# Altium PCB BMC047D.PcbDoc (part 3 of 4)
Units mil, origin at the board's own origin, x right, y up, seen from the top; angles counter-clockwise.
Board outline 4950 x 3450 mil, 6 copper layers (Top Layer, GND Layer 1, Signal Layer 1, Signal Layer 2, GND Layer 2, Bottom Layer), stack 60.7 mil thick; 323 components, 167 nets, 1114 pads, 795 vias.
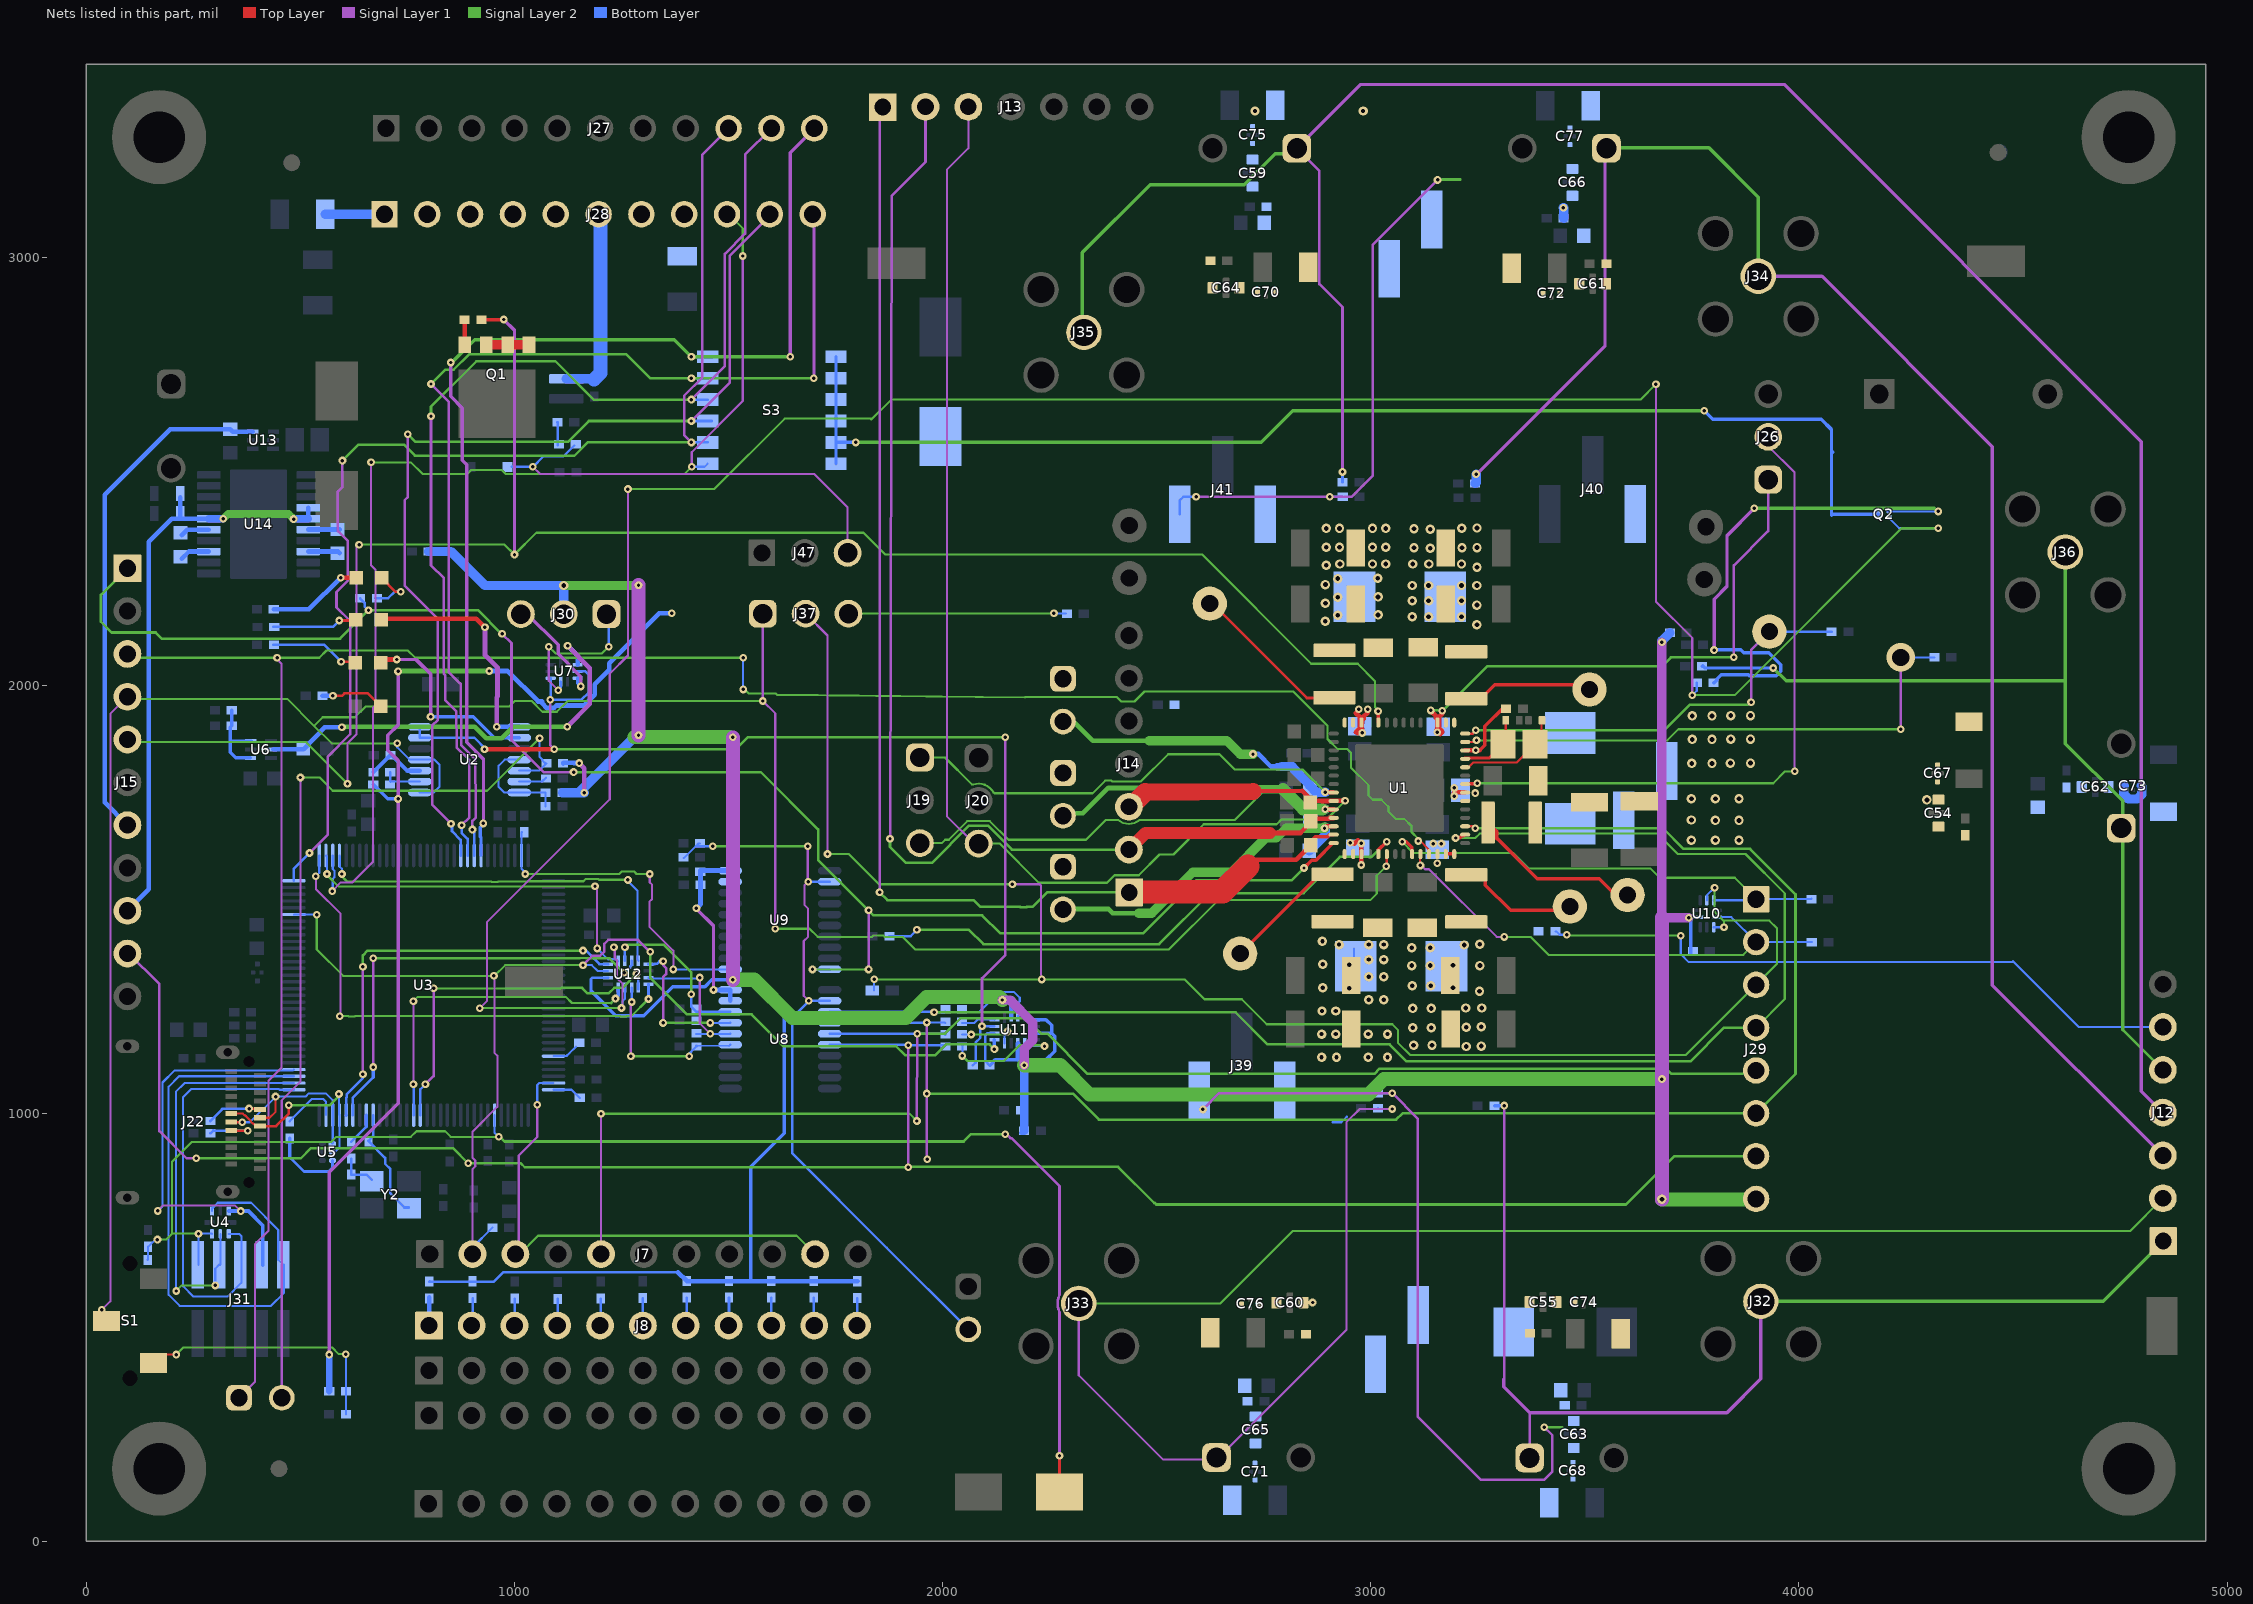
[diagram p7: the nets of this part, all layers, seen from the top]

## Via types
v1: diameter 18, hole 8, Top Layer to Bottom Layer, tented both sides, 520 vias
v2: diameter 22, hole 11, Top Layer to Bottom Layer, tented both sides, 196 vias
v3: diameter 22, hole 10, Top Layer to Bottom Layer, tented both sides, 36 vias
v4: diameter 19.68, hole 8, Top Layer to Bottom Layer, 21 vias
v5: diameter 19.68, hole 7.87, Top Layer to Bottom Layer, 9 vias
v6: diameter 19.68, hole 7.87, Top Layer to Bottom Layer, tented both sides, 6 vias
v7: diameter 20, hole 10, Top Layer to Bottom Layer, tented both sides, 3 vias
v8: diameter 18, hole 8, Top Layer to Bottom Layer, tented top, 2 vias
v9: diameter 18, hole 8, Top Layer to Bottom Layer, 1 vias
v10: diameter 66, hole 40, Top Layer to Bottom Layer, tented both sides, 1 vias

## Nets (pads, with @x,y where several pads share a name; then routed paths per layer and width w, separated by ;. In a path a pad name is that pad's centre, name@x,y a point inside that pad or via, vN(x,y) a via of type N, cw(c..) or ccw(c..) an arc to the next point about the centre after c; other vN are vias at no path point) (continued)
NetC92_1: C92.1 U3.88 Y2.1 | length 265.6
  Bottom Layer w6: U3.88@669.89,995.85 669.89,946.89 658.5,935.5 698,896 698,882.18 710,870.18 710,813 743,780 Y2.1@753,780
NetC95_1: C95.1 R50.2 Y2.3 | length 90.4
  Bottom Layer w6: R50.2@619,894.31 C95.1@619,856.68 654.5,856.68 Y2.3@666.69,844.5
NetC98_1: C98.1 R53.2 U8.19 U8.20 U9.19 U9.20 | length 459.3
  Signal Layer 1 w8: v1@1425,1477.69 1464.8,1437.88 v1(1464.8,1288.2)
  Signal Layer 1 w11: v1@1425,1477.69 v1(1425,1479)
  Bottom Layer w6: U9.20@1503.37,1567 U9.20@1503.86,1566.51
  Bottom Layer w11: v1(1425,1479) 1425.69,1479 1434.68,1488 1434.68,1536 1434.69,1567 U9.20@1503.37,1567 ; v1(1464.8,1288.2) U8.20@1503.86,1288.2 U8.19@1503.86,1262.61 ; U9.19@1503.86,1540.92 U9.20@1503.86,1566.51
NetC106_2: C106.2 R33.2 S1.1 | length 610.5
  Top Layer w5: S1.1@157.24,416.57 177.1,436.44 v1(210,436.44)
  Signal Layer 2 w5: v1(210,436.44) 226.5,452.94 574.15,452.94 589.5,437.59 605.41,437.59 v1(606,437)
  Bottom Layer w5: v1(606,437) 606.24,436.76 C106.2@606.24,297
NetC115_1: C115.1 U14.13 | length 70
  Bottom Layer w6: U14.13@285.83,2312.2 U14.13@286.02,2312.02
  Bottom Layer w11: C115.1@223,2295.44 239.76,2312.2 U14.13@285.83,2312.2
NetC115_2: C115.2 U14.15 | length 68.3
  Bottom Layer w11: C115.2@223,2350.56 235.65,2363.2 U14.15@286.02,2363.2
NetC116_1: C116.1 U14.8 | length 75.2
  Bottom Layer w11: U14.8@518.3,2312.02 588.42,2312.02 C116.1@592,2308.44
NetC116_2: C116.2 U14.6 | length 73.8
  Bottom Layer w11: U14.6@518.3,2363.2 518.65,2363.56 C116.2@592,2363.56
NetD1_1: D1.1 J47.3 R21.2 | length 1048.6
  Signal Layer 1 w5: v1(1042.93,2510) 1059.43,2493.5 1699.5,2493.5 1778,2415 J47.3@1778,2309
  Bottom Layer w5: D1.1@992.77,2510 v1(1042.93,2510) 1043.24,2509.69 1067.56,2534 1114,2534 R21.2@1140,2560
NetD3_1: D3.1 R22.1 | length 223.4
  Top Layer w11: v1(594,2251) D3.1@630.47,2251
  Bottom Layer w11: R22.1@437.68,2177 520,2177 v1(594,2251)
NetD3_2: D3.2 R35.2 | length 123.7
  Top Layer w6: D3.2@689.53,2251 722.53,2218 v1(734,2218)
  Bottom Layer w6: R35.2@674.69,2203 704.73,2203 719.73,2218 v1(734,2218)
NetD4_1: D4.1 R23.1 | length 199.8
  Top Layer w6: v1(591,2151) 627.47,2151 D4.1@629.47,2153
  Bottom Layer w6: R23.1@436.68,2136 437.68,2136 576,2136 v1(591,2151)
NetD4_2: D4.2 U2.1 | length 550.2
  Top Layer w11: D4.2@688.53,2153 690.53,2155 910.96,2155 v1(930.92,2135.04)
  Signal Layer 1 w11: v1(930.92,2135.04) 930.92,2070.66 960.5,2041.08 960.5,1974.01 958.23,1971.74 v1(958.23,1902.77)
  Bottom Layer w11: v1@958,1903 v1(958.23,1902.77) U2.1@1011.14,1902.77
NetD5_1: D5.1 R24.1 | length 209.2
  Top Layer w6: v1(595,2055) 625.47,2055 D5.1@628.47,2052
  Bottom Layer w6: R24.1@436.68,2094 556,2094 v1(595,2055)
NetD5_2: D5.2 U2.2 | length 465.9
  Top Layer w11: D5.2@679.53,2060 v1(725,2060)
  Signal Layer 1 w8: v1(725,2060) 770,2060 804,2026 v1(804,1926)
  Bottom Layer w8: v1(804,1926) 904,1926 952.82,1877.18 U2.2@1011.14,1877.18
NetD6_2: D6.2 R59.1 | length 150.8
  Top Layer w6: v1(576,1975) 597,1975 603,1981 657.53,1981 D6.2@687.53,1951
  Bottom Layer w11: R59.1@551.68,1975 v1(576,1975)
NetJ8_1: J8.1 R8.1 | length 69.1
  Bottom Layer w11: J8.1@801.18,501.18 R8.1@801.18,570.32
NetJ8_2: J8.2 R9.1 | length 65.1
  Bottom Layer w6: J8.2@900,504 902,506 R9.1@902,568.32
NetJ8_3: J8.3 R10.1 | length 63.7
  Bottom Layer w6: J8.3@1000,504 1001,505 R10.1@1001,567.32
NetJ8_4: J8.4 R11.1 | length 62.7
  Bottom Layer w6: J8.4@1100,504 1101,505 R11.1@1101,566.32
NetJ8_5: J8.5 R12.1 | length 63.7
  Bottom Layer w6: J8.5@1200,504 1201,505 R12.1@1201,567.32
NetJ8_6: J8.6 R13.1 | length 64.3
  Bottom Layer w6: J8.6@1300,504 R13.1@1300,568.32
NetJ8_7: J8.7 R14.1 | length 66.1
  Bottom Layer w6: J8.7@1400,504 1402,506 R14.1@1402,569.32
NetJ8_8: J8.8 R15.1 | length 65.7
  Bottom Layer w6: J8.8@1500,504 1501,505 R15.1@1501,569.32
NetJ8_9: J8.9 R16.1 | length 65.3
  Bottom Layer w6: J8.9@1600,504 R16.1@1600,569.32
NetJ8_10: J8.10 R17.1 | length 65.7
  Bottom Layer w6: R17.1@1699,569.32 1699,505 J8.10@1700,504
NetJ8_11: J8.11 R18.1 | length 64.7
  Bottom Layer w6: J8.11@1800,504 1801,505 R18.1@1801,568.32
NetJ21_2: J21.2 R28.1 U2.5 | length 2240
  Signal Layer 1 w5: J21.2@459,322 456.5,324.5 456.5,1030.17 499.99,1073.65 v1(499.99,1784.28)
  Signal Layer 2 w5: v1(499.99,1784.28) 544.78,1784.28 575.56,1753.5 936.02,1753.5 v1(1058.52,1876)
  Bottom Layer w5: U2.5@1011.14,1800.41 1057.54,1800.41 R28.1@1074.32,1817.18 1072.35,1817.18 1065,1824.52 1065,1826.49 1058.52,1832.98 v1(1058.52,1876)
NetJ22_A5: J22.A5 R41.1 | length 128.7
  Top Layer w6: v1(380,1011) 403.15,1011 404.15,1010 405.15,1009 J22.A5@405.45,1009.3
  Bottom Layer w6: R41.1@289.68,982 316.68,1009 317.68,1010 318.68,1011 v1(380,1011)
NetJ22_B5: J22.B5 R43.1 | length 129.6
  Top Layer w6: J22.B5@338.52,960.09 338.61,960 339.61,959 v1(377,959)
  Bottom Layer w6: R43.1@289.68,953 296.77,960.09 296.86,960 297.86,959 v1(377,959)
NetJ26_2: J26.2 U1.36 | length 1570.3
  Top Layer w8: U1.36@3217.22,1769.3 U1.36@3219.7,1769.3 ; U1.36@3219.81,1769.3 3247.7,1769.3 3249,1770.6 v1(3249,1771)
  Signal Layer 1 w5: J26.2@3928.37,2558.34 3990,2496.71 v1(3990,1798.59)
  Signal Layer 2 w5: v1(3249,1771) 3940,1771 3967.59,1798.59 v1(3990,1798.59)
NetJ30_1: J30.1 U7.7 | length 373.3
  Signal Layer 1 w5: v1(1080,2090) 1080,2009.91 v1(1101.91,1988)
  Signal Layer 2 w5: v1(1080,2090) 1096,2074 1204,2074 v1(1220,2090)
  Bottom Layer w5: v1(1101.91,1988) 1108.19,1994.28 U7.7@1108.19,2008.38 ; v1@1220,2088.04 J30.1@1220,2174.04
NetJ30_3: J30.3 U7.5 | length 258.2
  Signal Layer 1 w8: J30.3@1015,2166 1030,2166 1101.91,2094.09 1101.91,2073.09 1155,2020 v1(1155,1997)
  Bottom Layer w8: U7.5@1147.56,2016.25 1147.56,2004.44 v1(1155,1997)
NetJ37_3: J37.3 R30.2 | length 508.6
  Signal Layer 2 w5: J37.3@1780,2167 1780.63,2167.63 v1(2260,2167.63)
  Bottom Layer w5: v1(2260,2167.63) R30.2@2288.32,2167.63
NetJ38_2: J38.2 R55.1 R66.2 U8.2 U9.2 | length 1744.9
  Signal Layer 1 w5: v1(1685.86,1540.92) 1677,1532.07 1677,1487 1685.86,1478.14 1685.86,1412.6 1675.5,1402.25 1675.5,1274.5 v1(1687.39,1262.61)
  Signal Layer 1 w6: v1(1684.86,1624) 1684.86,1541.92 v1(1685.86,1540.92)
  Signal Layer 2 w6: v1(1463,1624) v1(1684.86,1624)
  Bottom Layer w5: R55.1@1395.32,1596 1423.32,1624 1429.63,1630.32 R66.2@1433.69,1630.32
  Bottom Layer w6: R66.2@1423.32,1624 v1(1463,1624) ; v1(1685.86,1540.92) U9.2@1736.14,1540.92 ; U8.2@1736.14,1262.61 v1(1687.39,1262.61) 1649,1224.21 1649,906.31 1869.31,686 J38.2@2059.94,495.37
NetJ39_1: J39.1 NT1.1 R2.2 | length 1809.5
  Signal Layer 1 w6: v1(2608,1009) 2646,1047 v8(3050.29,1047) 3109.54,987.75 3109.54,291.46 3257,144 3405,144 3424,163 3424,248 v1(3405,267)
  Signal Layer 2 w6: v1(3405,267) NT1.1@3447.5,267
  Bottom Layer w6: R2.2@3016.81,1047.21 3017.01,1047 v8(3050.29,1047)
NetJ41_1: J41.1 NT2.1 R6.2 | length 1349
  Signal Layer 1 w6: v1@2587.77,2440 v1(2592,2440) v1(2904,2440) 2955.31,2440 3005,2489.69 3005,2662 3005,3029 v1(3156,3180)
  Signal Layer 2 w6: v1(3156,3180) 3157,3181 NT2.1@3209,3181
  Bottom Layer w6: J41.1@2554,2399 2554,2432 2562,2440 v1(2592,2440) ; v1(2904,2440) R6.2@2934.57,2440
NetQ1_4: Q1.4 R26.2 | length 58.8
  Top Layer w11: Q1.4@884,2794.95 R26.2@884,2853.73
NetQ2_3: Q2.3 S3.1 S3.2 S3.3 S3.4 S3.5 S3.6 | length 2937.6
  Signal Layer 2 w8: v9(1796.9,2567) 2743.8,2567 2817.8,2641 v1(3779,2641)
  Bottom Layer w8: S3.6@1751,2517 S3.5@1751,2567 ; S3.1@1751,2767 S3.2@1751,2717 S3.3@1751,2667 S3.4@1751,2617 S3.5@1751,2567 ; v9(1796.9,2567) S3.5@1751,2567 ; v1(3779,2641) 3798.52,2621.48 4051.88,2621.48 4076.16,2597.2 4076.16,2547.2 ; 4079.16,2544.2 4076.16,2547.2 ; Q2.3@4184.89,2398.73 4077.69,2398.73 4076.16,2397.2 4076.16,2547.2
NetR20_2: R20.2 R21.1 | length 54.5
  Bottom Layer w6: R20.2@1100.31,2614.39 1100.63,2614.08 R21.1@1100.63,2560
NetR31_2: R31.2 R39.2 U6.1 U6.3 | length 198
  Bottom Layer w8: 339.69,1869.41 385.69,1869.41 U6.3@385.72,1869.37 ; R39.2@339.69,1941 R31.2@339.69,1905 336,1901.31 336,1843 349,1830 U6.1@383.03,1830
NetR37_1: R37.1 R38.2 U2.4 U2.7 | length 251.1
  Bottom Layer w5: U2.4@1011.14,1826 977,1826 963,1812 963,1762 975.77,1749.23 U2.7@1011.14,1749.23 1011.37,1749 R37.1@1072.73,1749 R38.2@1072.73,1717
NetR48_1: R48.1 U3.64 | length 69
  Bottom Layer w5: U3.64@1091.15,1054.91 1133.3,1054.91 R48.1@1152.31,1035.89
NetR50_1: R50.1 U3.89 | length 76.7
  Bottom Layer w6: R50.1@619,933.68 U3.89@654.14,968.83
  Bottom Layer w8: U3.89@654.14,968.83 U3.89@654.14,995.85
NetR51_2: R51.2 U1.41 | length 1277.1
  Top Layer w5: U1.41@3219.54,1867.27 U1.41@3220.54,1867.27 3243.27,1867.27 v1(3247,1871)
  Signal Layer 1 w5: v1(4237.91,1897) v10(4237.91,2065)
  Signal Layer 2 w5: v1(3247,1871) 3692.42,1871 3718.42,1897 v1(4237.91,1897)
  Bottom Layer w5: v10(4237.91,2065) R51.2@4316.33,2065
NetR52_1: R52.1 U3.59 | length 61.9
  Bottom Layer w5: U3.59@1091.15,1133.65 1121.65,1133.65 1128,1140 R52.1@1143.85,1155.85
NetR54_2: R54.2 U1.19 | length 1308.6
  Top Layer w8: U1.19@3016.94,1613.94 v1(3037,1634)
  Signal Layer 2 w6: v1(1940,1428.5) 2061.5,1428.5 2095,1395 2505.38,1395 2624.38,1514 2843,1514 2928,1599 3002,1599 v1(3037,1634)
  Bottom Layer w6: R54.2@1875.68,1414 1925.5,1414 v1(1940,1428.5)
NetR61_1: R61.1 U11.16 | length 79.5
  Bottom Layer w5: R61.1@2045.68,1211 2074.06,1211 2082.56,1219.5 2120.75,1219.5 U11.16@2120.75,1218.62
NetR62_1: R62.1 U11.3 | length 204
  Bottom Layer w5: R62.1@2045.68,1237.02 2085.93,1237.02 2131.92,1283 2167,1283 2180,1270 2180,1261 2177.16,1258.16 2177.16,1227.78 U11.3@2175.87,1226.5
NetR63_1: R63.1 U11.9 | length 288
  Signal Layer 2 w5: v1(2046,1134) 2058,1122 2142.46,1122 2179.46,1159 v1@2234.38,1159
  Bottom Layer w5: R63.1@2045.68,1158 2046,1157.68 v1(2046,1134) ; U11.9@2191.62,1163.5 2198.12,1157 ; U11.9@2192,1157 v1(2238,1157)
NetR64_1: R64.1 U11.12 | length 139.5
  Signal Layer 2 w5: v1(2067,1184) 2144.22,1184 v1(2151.46,1191.24)
  Bottom Layer w5: R64.1@2045.68,1184 v1(2067,1184) ; U11.12@2144.38,1163.5 2144.38,1181 2151.46,1188.09 v1(2151.46,1191.24)
NetR83_2: R83.2 U2.6 | length 66.2
  Bottom Layer w5: U2.6@1011.14,1774.82 1064.32,1774.82 R83.2@1073.5,1784
NetR93_2: R93.2 R94.2 U2.9 | length 91.7
  Bottom Layer w5: R94.2@709.69,1797 709.69,1774.78 710,1774.46 710.36,1774.82 U2.9@778.86,1774.82
NetR94_1: R94.1 R95.1 U2.10 | length 140.7
  Bottom Layer w9: R94.1@670.32,1797 709.32,1836 R95.1@710.68,1836 ; R95.1@710.68,1839 749.28,1800.41
  Bottom Layer w11: 749.28,1800.41 U2.10@778.86,1800.41
nINT: J15.1 R35.1 U1.14 U9.10 | length 3993.4
  Top Layer w8: v1(2844,1573) 2862,1591 2872.11,1591 U1.14@2912.61,1631.5
  Signal Layer 1 w6: v1(971,2120) 993,2098 993,1872.24 1068.24,1797 v1(1138,1797) ; v1(1827,1336) v1(1827,1474)
  Signal Layer 2 w5: v1(1696,1336) v1@1824,1336
  Signal Layer 2 w6: J15.1@96,2273 34,2211 34,2148.11 59.11,2123 161.68,2123 175.84,2108.84 592.84,2108.84 v1(659,2175) 915,2175 970,2120 v1(971,2120) ; v1(1138,1797) 1575.19,1797 1709.19,1663 1709.19,1591.81 1838.5,1462.5 2092.35,1462.5 2134.7,1420.15 2468.15,1420.15 2592,1544 2815,1544 v1(2844,1573)
  Bottom Layer w5: v1(1696,1336) 1735.94,1336 U9.10@1736.14,1336.2
  Bottom Layer w6: R35.1@639.32,2202.72 650,2192.03 650,2184 v1(659,2175) ; v1@1133.68,1797 v1(1138,1797)
nINT3P3: R44.2 U3.31 U9.11 | length 781.2
  Signal Layer 1 w5: v1(1316,1559) 1316,1539 1321.5,1533.5 1321.5,1500.5 1315,1494 1315,1435.9 1371,1379.9 v1(1371,1336)
  Signal Layer 2 w5: v1(1025,1559) 1245,1559 1251,1565 1279,1565 1285,1559 v1(1316,1559)
  Bottom Layer w5: R44.2@1017,1656.31 1016.35,1655.66 U3.31@1016.35,1602.15 1016.35,1571.25 1025,1562.6 v1(1025,1559) ; v1(1371,1336) 1503.66,1336 U9.11@1503.86,1336.2
nPWRON: J15.4 J37.1 S1.2 U1.20 U2.8 U2.11 | length 5815.6
  Top Layer w5: v1(36,541) 36,526 S1.2@47,515 ; v1(3036,1577) 3037.47,1578.47 U1.20@3037.47,1605.46
  Signal Layer 1 w5: v1(36,541) 56,561 56,1933 J15.4@96,1973 ; J37.1@1580,2167 v1(1580,1963) 1609,1934 v1(1609,1431)
  Signal Layer 2 w5: J15.4@96,1973 101,1968 469,1968 531.5,1905.5 ; v1(726,1864) 573,1864 531.5,1905.5 ; v1(1580,1963) 1124,1963 1099,1938 1065,1938 1040,1963 1000.42,1963 987.42,1950 652.25,1950 627.25,1925 552,1925 532.5,1905.5 531.5,1905.5 ; v1(1609,1431) 1689,1431 1708,1412 1835.11,1412 1838.61,1415.5 1861.39,1415.5 1864.89,1412 1906.45,1412 1935.95,1382.5 2528.5,1382.5 2643.82,1497.82 2998.82,1497.82 3014,1513 3014,1555 v1(3036,1577)
  Bottom Layer w5: v1(726,1864) 726,1855.09 755.09,1826 U2.11@778.86,1826 813,1826 825,1814 825,1763 811.23,1749.23 U2.8@778.86,1749.23
nPWRON_S: J29.3 J37.2 R34.2 U10.4 U10.8 | length 4024.1
  Signal Layer 1 w5: J37.2@1680,2167 1731,2116 v1(1731,1605.67) ; v1(2163,1535) 2226.83,1535 2229.76,1532.07 2229.76,1314.07 v1(2231.16,1312.67)
  Signal Layer 2 w5: v1(1731,1605.67) 1780.83,1605.67 1851.5,1535 v1(2163,1535) ; v1(1840,1313) v1(2231.16,1312.67) 2371,1312.55 2565.62,1312.38 2611.5,1266.5 2698.5,1266.5 2757,1208 3050,1208 3064,1194 3064,1164 3092,1136 3736,1136 3949,1349 3949,1432 3931,1450 3824,1450 ; v1(3803,1527) 3803,1471 3824,1450 ; v1(3825,1434.5) 3825,1449 3824,1450
  Bottom Layer w5: R34.2@1839.31,1287 1839.31,1312.31 v1(1840,1313) ; U10.4@3785,1497.5 3785,1509 v1(3803,1527) ; U10.8@3800.75,1434.5 v1(3825,1434.5)
nRST_MCU: C82.1 J31.10 R47.1 S2.2 U3.70 U4.7 | length 3378.4
  Top Layer w5: v1@2272,201 v1(2273,200)
  Top Layer w6: S2.2@2273,115 v1(2273,200)
  Signal Layer 1 w6: v1(2146,951.12) 2149.25,951.12 2158.37,942 2161,942 2273,830 2273,576.23 ccw(c2318,556) 2273,535.77 v1(2273,200)
  Signal Layer 2 w5: v1(166,705) 186,705 200,719 ; v1(262,719) 200,719 ; v1(963,945) 851,945 838,958 771,958 758,945 584,945 572,933 246,933 200,887 200,719
  Signal Layer 2 w6: v1(963,945) 966.25,945 977.13,934.12 2049.04,934.12 2066.04,951.12 v1(2146,951.12)
  Bottom Layer w5: C82.1@143,657.68 144,658.68 R47.1@144,688.32 144.32,688.32 162,706 164,704 165,705 v1(166,705) ; J31.10@262,645.53 v1(262,719) 292.74,719 U4.7@293.31,718.43 ; U3.70@953.35,995.85 953.35,954.65 v1(963,945)
nRSTOUT: J15.3 J21.1 U1.25 | length 5163
  Top Layer w5: v1(3111,1636) 3111,1637 3112,1638 3113,1637 3114,1638 3134.9,1617.1 U1.25@3134.9,1605.46
  Signal Layer 1 w5: J21.1@356.5,335.56 393.5,372.56 393.5,694.02 425.5,726.02 425.5,1075.73 455.5,1105.73 455.5,2050.7 445.46,2060.74 v1(445.46,2064)
  Signal Layer 2 w5: J15.3@96,2073 105,2064 v1(445.46,2064) 544,2064 561,2081 751,2081 768,2064 v1(1534,2064) ; J15.3@96,2098.5 J15.3@96,2100 ; v1(1534,1990) 1537.52,1990 1547.08,1980.44 1610.06,1980.44 1613,1977.5 2192.15,1971 2193.67,1972.52 2406.48,1972.52 2417,1962 2448,1962 2471.34,1985.34 2818.66,1985.34 2899,1905 2899,1874.42 2922.92,1850.5 2945.5,1850.5 2954,1842 2954,1807 2995,1766 2995,1742 3004.5,1732.5 3024.5,1732.5 3041,1716 3041,1705 3059,1687 3079,1687 3095,1671 3095,1657 3111,1641 v1(3111,1636)
  Bottom Layer w5: v1(1534,1990) v1(1534,2064)
OSC32KCAP: C23.1 U1.40 | length 159.1
  Top Layer w8: 3254.04,1848.04 3266,1860 3266,1903.68 C23.1@3311.32,1949
  Top Layer w11: U1.40@3219.7,1848.04 3219.74,1848 v1(3245,1848) 3254,1848 3254.04,1848.04
OSC32KIN: C17.2 U1.38 Y1.1 | length 232.2
  Top Layer w5: U1.38@3229.03,1808.67 3239.75,1819.39 3340.79,1819.39 Y1.1@3383.4,1862 ; Y1.1@3391,1874.79 3398.75,1882.54 C17.2@3398.75,1918
  Top Layer w6: U1.38@3219.7,1808.67 U1.38@3229.03,1808.67
OSC32KOUT: C16.2 U1.39 Y1.2 | length 167.5
  Top Layer w6: U1.39@3219.7,1828.35 3219.7,1829.89 3276.48,1829.89 Y1.2@3308.6,1862 3315.25,1868.65 C16.2@3315.25,1918 ; Y1.2@3284.79,1862 Y1.2@3284.79,1867
OVPGDRV: J15.5 R26.1 U1.52 | length 4384.6
  Top Layer w7.87: R26.1@922.68,2853.73 974.83,2853.73 v1(975.1,2854)
  Top Layer w8: U1.52@3016.94,1913 3017,1913.06 v1(3017,1939)
  Signal Layer 1 w5: v1(610,1770) 610,1864.27 631,1885.27 631,2322.2 v1(637,2328.2)
  Signal Layer 1 w7.87: v1(975.1,2854) 1000,2829.1 v1(1000,2305)
  Signal Layer 2 w5: J15.5@96,1873 102,1867 513,1867 v1(610,1770) ; v1(637,2328.2) 976.8,2328.2 v1(1000,2305) 1051,2356 1815,2356 1866,2305 2606,2305 2861,2050 2969.48,2050 3010,2009.48 3010,1949 3017,1942 v1(3017,1939)
PB0: R45.1 U3.95 | length 140.9
  Bottom Layer w5: R45.1@475,980.68 475,982 526,1033 554,1033 559.65,1027.35 U3.95@559.65,995.85
PVIN_LDO3: C5.1 J17.2 J19.3 U1.10 | length 1636.8
  Top Layer w9: v1@2890.79,1709.79 2891,1710 v1(2894,1710)
  Top Layer w11: v1@2890.79,1709.79 U1.10@2913.46,1709.79
  Signal Layer 2 w5: J19.3@1947,1631 1998,1631 2006,1639 2014.15,1639 2057.65,1682.5 2110.35,1682.5 2153.85,1639 2335,1639 2381,1685 2409.75,1685 ccw(c2435,1716) 2460.25,1685 2682.01,1685 2754.01,1757
  Signal Layer 2 w11: J17.2@2281,1695 2286.68,1700.68 2327.62,1700.68 2386.94,1760 2476,1760
  Signal Layer 2 w20: 2476,1757 2754.01,1757 2795,1757
  Signal Layer 2 w22: v1@2887,1710 2889,1708 2891,1710 v1(2894,1710)
  Signal Layer 2 w28: 2795,1757 2842,1710 v1@2887,1710
  Bottom Layer w22: C5.1@2854.56,1688 2876.8,1710.24 2879.05,1708 2881.05,1710 v1(2894,1710)
PVIN_LDO4: C6.1 J18.2 J19.1 U1.8 | length 1730.6
  Top Layer w11: v1@2891.77,1749 v1@2892.39,1749.61 ; v1(2893.31,1750.31) 2893.08,1750.31 v1@2892.39,1749.61 ; U1.8@2912.61,1749.61 v1@2892.39,1749.61
  Signal Layer 2 w5: J19.1@1947,1831 2005.45,1831 2067.05,1769.4 2068.52,1767.93 2070.59,1767.93 2071.38,1767.93 cw(c2084,1730) 2118.93,1749.44 2119.41,1748.96 2120.88,1747.5 2350.26,1747.5 2379.86,1777.09 2394.08,1777.09 2396.17,1775 2463,1775 2526.74,1838.74 2646.63,1838.74 2682.5,1802.87 2691.2,1802.87 2691.33,1803 2840.61,1803 v1(2893.31,1750.31)
  Signal Layer 2 w11: J18.2@2305,1915.46 2350.46,1870 2483,1870
  Signal Layer 2 w22: 2483,1870 2660,1870 ; 2664,1870 2695,1839 v1(2725,1839)
  Bottom Layer w11: v1(2725,1839) 2737.82,1839 2766.82,1810 2782,1810
  Bottom Layer w18: 2782.38,1809.62 2789.77,1809.62
  Bottom Layer w22: 2792,1810 2817.14,1810 ; 2816.87,1807.66 C6.1@2857.54,1766.98 ; C6.1@2856.56,1766 2873.56,1749 2874.87,1750.31 v1(2893.31,1750.31)
PVIN_LDO12: C4.1 J16.2 U1.12 | length 769.6
  Top Layer w11: v1(2892,1666) 2896.42,1670.42 U1.12@2913.46,1670.42
  Signal Layer 2 w11: J16.2@2305,1477 2387.47,1477 2396.95,1467.52 2458.04,1467.52
  Signal Layer 2 w22: 2458.04,1467.52 2488.65,1467.52 2584.13,1563 2674.18,1563 2754.18,1643 2779.4,1643 2802.4,1666 v1(2892,1666) ; v1@2890.39,1667.77 v1@2893.49,1667.77
  Bottom Layer w22: C4.1@2856.56,1613 2893.49,1649.93 v1@2893.49,1667.77
S/P: R29.2 U2.13 U2.14 U7.4 U7.8 U11.15 | length 2586.9
  Top Layer w11: v1(930,1850) v1(1093,1850)
  Signal Layer 1 w6: v1(1083.83,1966) 1083.83,1859.17 v1(1093,1850) ; v1(2092,1203) 2092,1315 2146,1369 v1(2146,1878.5)
  Signal Layer 2 w6: v1(1093,1850) 1516.64,1850 1545.14,1878.5 v1(2146,1878.5)
  Bottom Layer w6: U2.14@778.86,1902.77 U2.13@778.86,1877.18 906.33,1877.18 933.51,1850 v1(930,1850) ; U7.8@1084.57,2016.25 1084.57,1966.74 v1(1083.83,1966) 1156.35,1966 1173.73,1983.38 1173.73,2023.79 1165.52,2032 U7.4@1147.56,2032 ; R29.2@2070.31,1111.96 2077,1118.65 2077,1165.54 2087.94,1176.49 2087.94,1198.94 v1(2092,1203) 2120.63,1203 U11.15@2120.75,1202.87
SCL1: U3.91 U12.3 | length 1023.1
  Signal Layer 1 w6: v1(670,1108) v1(670,1362)
  Signal Layer 2 w5: v1(670,1362) 1152.67,1362 1153.17,1362.5 1166.83,1362.5 1167.33,1362 1222,1362
  Signal Layer 2 w6: 1222,1362 v1(1256,1328)
  Bottom Layer w6: U3.91@622.65,995.85 622.65,1036.65 670,1084 ; v1(1256,1328) 1263.56,1335.56 1265.55,1335.56 1270.82,1340.83 1270.82,1342.82 1273.63,1345.63 U12.3@1273.63,1356.37
  Bottom Layer w8: 670,1084 v1(670,1108)
SCL1/SCK: R71.2 U8.17 U12.5 | length 380.5
  Signal Layer 1 w6: v1(1347,1211) 1347,1317.96 1354,1324.96 1354,1339.04 1347,1346.04 v1(1347,1355)
  Signal Layer 2 w6: v1(1347,1211) v1(1457,1211)
  Bottom Layer w5: R71.2@1424.69,1211 v1(1457,1211) 1503.43,1211 U8.17@1503.86,1211.43
  Bottom Layer w6: U12.5@1313,1348.5 1327.45,1348.5 1327.96,1349 1332.74,1349 1338.74,1355 v1(1347,1355) ; R71.2@1420,1211 R71.2@1424.69,1211
SCL2: U3.82 U12.12 | length 783.9
  Signal Layer 1 w5: v1@760,1068 764,1072 v1(764,1262)
  Signal Layer 2 w5: v1(764,1262) 773.87,1271.87 1120.07,1271.87 1134.44,1257.5 1225.5,1257.5
  Signal Layer 2 w6: 1225.5,1257.5 v1(1236,1268)
  Bottom Layer w6: v1@760,1068 764.38,1063.62 U3.82@764.38,995.85
  Bottom Layer w8: v1(1236,1268) 1242.13,1274.13 U12.12@1242.13,1293.38
  other v1: 764,1068
SCL2/CS: R73.2 U8.15 U12.10 | length 419
  Signal Layer 1 w6: v1(1272,1133) 1272,1258 v1(1274,1260)
  Signal Layer 2 w6: v1(1272,1133) v1(1408,1133)
  Bottom Layer w5: R73.2@1423.69,1158 1425.7,1157.97 1500.61,1157 U8.15@1503.86,1160.24
  Bottom Layer w6: U12.10@1273.63,1293.38 1273.63,1270.37 v1(1274,1260) ; v1(1408,1133) 1401.69,1133 R73.2@1425.69,1157
SCL_I2C1/SCK_SPI: J29.6 R61.2 U1.31 U8.4 | length 3946.2
  Top Layer w6: U1.31@3219.7,1670.87 v1@3239.67,1670.87
  Signal Layer 1 w6: v1(1963,1212) v1(1963,1046) 1963,895 v1@1964,894
  Signal Layer 2 w6: v1(1963,1046) 2304,1046 2365,985 3059.2,985 3074.2,1000 J29.6@3900,1000 3992,1092 3992,1511.19 3885.78,1617.41 3730.59,1617.41 3682,1666 v1(3244,1666) ; v1(3244,1666) 3242.04,1666 3244,1667.96 v1(3244,1666)
  Bottom Layer w5: U8.4@1736.44,1211.72 U8.4@1736.14,1211.43 1962.43,1211.43 v1(1963,1212) 2005.31,1212 R61.2@2006.31,1211
  other v1: 1964,893
SCL_I2C2/CS_SPI: J15.10 J29.7 R63.2 U8.6 | length 4897.7
  Signal Layer 1 w6: J15.10@96,1400 96,1376 170.46,1301.54 170.46,958.54 234,895 v1(257,895) ; v1(1920,874) v1(1920,1159)
  Signal Layer 2 w6: v1(257,895) 501,895 524,918 857,918 v1(892,883) 1015,883 1024,874 v1(1920,874) 1920,875 2409.8,875 2494.3,790.5 2495.5,790.5 2499,787 3596,787 3709,900 J29.7@3900,900
  Bottom Layer w5: U8.6@1737.16,1159.22 U8.6@1736.14,1160.24 1918.76,1160.24 v1(1920,1159) 2005.31,1159 R63.2@2006.31,1158
SCLK_SPMI: J29.1 R68.2 U1.23 U10.5 | length 1161.8
  Top Layer w7.87: v1(3073.75,1634.07) 3082.93,1634.07 3095.68,1621.32 U1.23@3095.68,1605.91
  Signal Layer 1 w5: J29.1@3893.87,1506.13 J29.1@3900,1500
  Signal Layer 2 w5: v1(3073.75,1634.07) 3099.83,1608 3333,1608 3369,1572 3653,1572 3675,1550 3850,1550 J29.1@3900,1500
  Bottom Layer w5: U10.5@3800.75,1497.5 3895.5,1497.5 J29.1@3899,1501 ; J29.1@3900,1500.19 R68.2@4029,1500.19
SDA1: U3.92 U12.16 | length 971.5
  Signal Layer 1 w6: v1(646,1091) v1(646,1342)
  Signal Layer 2 w6: v1(646,1342) 646,1369 657,1380 v1(1160,1380)
  Bottom Layer w6: U3.92@607,995.95 607,1036.54 608,1037.54 608,1044 646,1082 ; v1(646,1091) v1@647,1091 ; v1(1160,1380) 1167,1380 1198.5,1348.5 U12.16@1218.51,1348.5
  Bottom Layer w8: U3.92@606.9,995.85 U3.92@607,995.95
SDA1/SDI: R70.2 U8.18 U12.2 | length 392.2
  Signal Layer 2 w6: v1(1257.88,1388) 1263.88,1394 1348,1394 1413,1329 v1(1413,1278)
  Bottom Layer w6: U12.2@1257.88,1356.37 v1(1257.88,1388) ; v1(1413,1278) 1413,1248.7 1424.69,1237.02 U8.18@1503.86,1237.02
SDA2: U3.81 U12.9 | length 850.7
  Signal Layer 1 w6: v1(792,1068) 811,1087 v1(811,1292)
  Signal Layer 2 w6: v1(811,1292) 1107.2,1291 1109.2,1293 1157.86,1293 1170.86,1280 1220,1280 1233,1293 1252,1293 v1(1285,1326) v1@1289,1326
  Bottom Layer w6: U3.81@780.13,995.85 780.13,1056.13 v1(792,1068) ; v1(1285,1326) 1289.38,1321.62 U12.9@1289.38,1293.38 U12.9@1289.38,1289.31
SDA2/SDO: R72.2 U8.16 U12.7 | length 343.8
  Signal Layer 1 w5: v1(1432.69,1317) 1432.69,1210.38 v1(1457.06,1186)
  Bottom Layer w5: U12.7@1313,1317 1313,1314.5 1430.19,1314.5 v1(1432.69,1317) ; R72.2@1424.69,1185 1503.02,1185 U8.16@1503.86,1185.83
SDA_I2C1/SDI_SPI: J29.4 R62.2 U1.30 U8.3 | length 3465.6
  Top Layer w8: v1(3198,1643) 3206,1643 3207.77,1644.77 3210.28,1644.77 U1.30@3212.51,1647 ; U1.30@3215.51,1648 3216.01,1648.5 3216.51,1648 U1.30@3219.7,1651.19
  Signal Layer 2 w5: v1(3198,1643) 3244.33,1643 3254.6,1653.27 3669.73,1653.27 3717.33,1605.67 3875.11,1605.67 3967,1513.78 3967,1267 J29.4@3900,1200
  Signal Layer 2 w6: v1(1980,1236) 2684,1236 2759,1161 3044,1161 3083.5,1121.5 3746.78,1121.5 3825.28,1200 J29.4@3900,1200
  Bottom Layer w6: U8.3@1736.14,1237.02 1978.98,1237.02 v1(1980,1236) 2005.3,1236 R62.2@2006.31,1237.02
SDA_I2C2/SDO_SPI: J7.5 J29.5 R64.2 U8.5 | length 3589.6
  Signal Layer 1 w5: J7.5@1202,671 v1(1202,999)
  Signal Layer 1 w6: v1(1940,982) v1(1941,1186)
  Signal Layer 2 w5: v1(1202,999) 1923,999 v1(1940,982)
  Signal Layer 2 w6: v1(1941,1186) 2006,1186 2042,1222 2194,1222 2230,1186 2244.5,1186 2338.52,1091.98 2969.93,1091.98 2984.04,1092 3008.33,1091.98 3020.85,1104.5 3690.15,1104.5 3702.67,1091.98 3891.98,1091.98 J29.5@3900,1100
  Bottom Layer w6: U8.5@1736.14,1185.83 1940.83,1185.83 v1(1941,1186) 2004.31,1186 R64.2@2006.31,1184
SDATA_SPMI: J29.2 R69.2 U1.24 U10.7 | length 1157.1
  Top Layer w5: U1.24@3115.21,1605.46 3115.21,1578.79 3116,1578 v1(3116,1579)
  Signal Layer 1 w5: v1(3116,1579) 3117.72,1579 3126.78,1569.94 3136.06,1569.94 3294,1412 v1(3312,1412)
  Signal Layer 2 w5: v1(3312,1412) 3373,1412 3415,1370 3870,1370 J29.2@3900,1400
  Bottom Layer w5: U10.7@3808.62,1458.13 3841.87,1458.13 J29.2@3900,1400 R69.2@4029.85,1400
SPI_CLK: U3.4 U12.4 | length 935.1
  Signal Layer 2 w5: v1(597,1559) 592.7,1559 592,1558.3 608.8,1541.5 945.75,1541.5 946.75,1540.5 961.25,1540.5 962.25,1541.5 1032.25,1541.5 1032.75,1542 1161,1542 1166.5,1547.5 1195.25,1547.5 1197.25,1545.5 1261.5,1545.5 v1@1265,1542
  Bottom Layer w5: U3.4@591.15,1602.15 592,1601.3 592,1575.84 597,1570.84 v1(597,1559) ; v1(1265,1545) 1265,1541.78 1287.5,1519.28 1287.5,1358.25 U12.4@1289.38,1356.37
SPI_CS: Q2.2 R19.2 U12.11 | length 6051
  Signal Layer 1 w5: v1(919.05,1245.58) 935.5,1262.03 935.5,1446.17 1222.5,1733.17 1222.5,2026.83 1265,2069.33 v1(1265,2458.03) ; v1(1232.28,1388) 1234.12,1386.16 1234.12,1362.41 1239.37,1357.17 1239.37,1315.73 1252.5,1302.6 1252.5,1261.17 1252.49,1248.49 v1(1250,1246) ; v1@3666,2706 v1(3666,2703.01) 3666,2195.56 3751,2110.56 v1(3751,1976.68)
  Signal Layer 2 w5: v1(919.05,1245.58) 1249.58,1245.58 v1(1250,1246) ; v1(1265,2458.03) 1466.62,2458.03 1631.05,2622.46 1832.68,2622.46 ; 1832.68,2620.07 1879.61,2667 3629.99,2667 v1(3666,2703.01) ; v1(3751,1976.68) 3849.86,1976.68 4239.54,2366.37 v1(4325.71,2366.37)
  Bottom Layer w5: v1(1250,1246) 1252.49,1248.49 1252.49,1261.15 1252.5,1261.83 1257.88,1267.22 U12.11@1257.88,1293.38 ; v1(3751,1976.68) 3761.31,1987 R19.2@3761.31,2006 ; Q2.2@4210.95,2389.68 4234.27,2366.37 v1(4325.71,2366.37)
SPI_CS0: J28.9 S3.7 U3.3 | length 2620.7
  Signal Layer 1 w5: v1@576,1519 v1(574,1519) 594.33,1539.33 621.66,1539.33 669.14,1586.8 669.14,1946.74 675.5,1953.1 675.5,2269.43 664.96,2279.97 v1(664.96,2520.47) ; v1(1413.86,2510) 1413.86,2544.27 1533.14,2663.55 v1(1533.14,3002.43)
  Signal Layer 2 w5: v1(664.96,2520.47) 758.04,2520.47 785,2493.5 890.17,2493.5 899.32,2502.65 969.96,2502.65 979.12,2493.5 1397.36,2493.5 v1(1413.86,2510) ; J28.9@1500,3100 1533.14,3066.86 v1(1533.14,3002.43)
  Bottom Layer w5: v1(574,1519) 575.4,1520.4 575.4,1547.65 579.5,1551.75 579.5,1566.25 575.4,1570.35 U3.3@575.4,1602.15 ; v1(1413.86,2510) 1444,2510 S3.7@1451,2517
SPI_CS1: J27.9 S3.8 U3.128 | length 2749.6
  Signal Layer 1 w6: v1(521.17,1607.93) 563.89,1650.65 563.89,1833.01 616.4,1885.52 616.4,2149.64 584.2,2181.84 584.2,2217.16 611,2243.96 611,2336.34 587.46,2359.88 587.46,2452.27 598.15,2462.96 v1(598.15,2524.58) ; v1(1413.25,2567) 1396.25,2584 1396.25,2675.96 1438.91,2718.61 1438.91,3238.91 J27.9@1500,3300
  Signal Layer 2 w6: v1(598.15,2524.58) 635.57,2562 741.55,2562 767.37,2536.17 1139.56,2535.74 1170.82,2567 v1(1413.25,2567)
  Bottom Layer w6: U3.128@484.85,1543.09 484.85,1571.6 v1(521.17,1607.93) ; v1(1413.25,2567) S3.8@1451,2567
SPI_CS2: J28.10 S3.9 U3.22 | length 2349.9
  Signal Layer 1 w6: v1(751,2586) 751,2439.54 743.31,2431.86 743.31,2232.73 821,2155.04 821,1918.96 807.49,1905.45 807.49,1720.75 v1(851.72,1676.52) ; v1(1413.25,2617) 1502.43,2706.18 1502.43,3002.43 J28.10@1600,3100
  Signal Layer 2 w6: v1(751,2586) 768,2569 1125.67,2569 1173.67,2617 v1(1413.25,2617)
  Bottom Layer w6: v1(851.72,1676.52) 854.02,1674.22 854.02,1658.92 874.26,1638.69 874.26,1602.51 U3.22@874.61,1602.15 ; v1(1413.25,2617) S3.9@1451,2617 S3.9@1461.04,2617
SPI_CS3: J27.10 S3.10 U3.23 | length 2535.6
  Signal Layer 1 w6: v1(805,2628) 805,2279.86 835,2249.86 835,2026.44 837.93,2023.51 837.93,1964.96 853.97,1948.92 864.24,1938.65 864.87,1859.42 864.87,1854.91 893.87,1825.9 893.89,1823.44 894.53,1743.23 ; v1(876.4,1673) 894.53,1691.13 894.53,1743.16 ; v1(1413.25,2667) 1491.43,2745.18 1491.43,3006.99 1538.91,3054.46 1538.91,3238.91 J27.10@1600,3300
  Signal Layer 2 w6: v1(805,2628) 805,2650.62 910.88,2756.5 1095.4,2756.5 1184.9,2667 v1(1413.25,2667)
  Bottom Layer w6: v1(876.4,1673) 876.4,1655 890.36,1641.04 U3.23@890.36,1602.15 ; v1(1413.25,2667) S3.10@1451,2667
SPI_CS4: J28.11 S3.11 U3.24 | length 2516.4
  Signal Layer 1 w6: v1(805,2703.43) 846,2662.43 846,2031 872.98,2004.02 874.74,2002.26 875.87,1859.46 907.06,1828.27 908.79,1826.54 909.71,1711 909.71,1690.75 901.71,1682.75 v1(901.71,1662.74) ; v1(1699,2717) 1699.5,2717.5 1699.5,3099.5 J28.11@1700,3100
  Signal Layer 2 w6: v1(805,2703.43) 838.61,2737.04 843.58,2737.04 843.96,2736.66 858.04,2736.66 894.38,2773 1260.66,2773 1316.66,2717 v1(1413.25,2717) v1(1699,2717)
  Bottom Layer w6: v1(901.71,1662.74) 901.71,1659.49 906.11,1655.09 U3.24@906.11,1602.15 ; v1(1413.25,2717) S3.11@1451,2717
SPI_CS5: J27.11 S3.12 U3.25 | length 2622.7
  Signal Layer 1 w8: v1(851,2753.66) 851,2674.4 878,2647.4 878,2525.18 888.15,2515.03 888.15,1866.39 927.69,1826.86 927.69,1677.99 v1(926.71,1677.01) ; v1(1644,2767) 1644,3244 J27.11@1700,3300
  Signal Layer 2 w8: v1(851,2753.66) 853.71,2753.66 907.05,2807 1373.25,2807 v1(1413.25,2767) v1(1644,2767)
  Bottom Layer w8: U3.25@921.86,1602.15 921.86,1643.87 920.18,1645.55 920.18,1667.77 926.71,1674.3 v1(926.71,1677.01) ; v1(1413.25,2767) S3.12@1451,2767 S3.12@1461.04,2767
SPI_EN: J7.2 R46.2 U3.123 U11.13 U12.15 | length 2799.6
  Signal Layer 1 w5: J7.2@902,671 902,869.67 908.5,876.17 908.5,889.83 902,896.33 902,957 960,1015 960,1134.5 953,1141.5 953,1320 v1(952,1321)
  Signal Layer 1 w6: v1(1160,1346) 1182,1368 1200.04,1368 1210,1377.96 1210,1396 1219,1405 1289,1405 v8(1317,1377)
  Signal Layer 2 w5: v1(538,1464) 538,1384 537.5,1383.5 600,1321 v1(952,1321) 953.25,1321 978.25,1346 v1(1160,1346)
  Signal Layer 2 w6: v8(1317,1377) 1317,1317 1403,1231 1553.91,1231 1628.36,1156.54 1891.7,1156.54 1912.24,1136 1983,1136 2008,1161 2110,1161 v1(2121,1150)
  Bottom Layer w5: U3.123@484.85,1464.35 485.2,1464 v1(538,1464) ; J7.2@902,671 902,686.69 R46.2@948.31,733 ; v1(1160,1346) 1180.5,1346 1193.75,1332.75 U12.15@1218.51,1332.75
  Bottom Layer w8: U11.13@2120.75,1171.38 2121,1171.13 v1(2121,1150)
SPI_MISO: U3.1 U12.8 | length 1175.9
  Signal Layer 1 w5: v1(536,1554) 536,1524 594,1466 594,1229 v1(592,1227)
  Signal Layer 2 w5: v1(592,1227) 612.25,1227 612.75,1226.5 627.25,1226.5 627.75,1227 1246.25,1227 1246.75,1226.5 1261.25,1226.5 1261.75,1227 1273,1227 v1(1313,1267)
  Bottom Layer w5: v1(536,1554) 543.91,1561.91 U3.1@543.91,1602.15
  Bottom Layer w6: v1(1313,1267) U12.8@1313,1301.25
SPI_MOSI: U3.2 U12.1 | length 891.8
  Signal Layer 1 w5: v1(1188,1530) 1193,1525 v1(1193,1385)
  Signal Layer 2 w5: v1(562,1559) 562,1556.65 588.65,1530 941.69,1530 942.19,1529.5 965.81,1529.5 966.31,1530 v1@1187,1530
  Bottom Layer w5: U3.2@559.65,1602.15 562,1599.8 v1(562,1559) ; v1(1193,1385) 1218.07,1359.93 1236.6,1359.93 U12.1@1242.13,1354.4
SW_B1: L1.1 TP9.1 U1.27 U1.28 | length 248.1
  Top Layer w7.87: U1.27@3174.43,1605.91 U1.28@3194.11,1605.91 ; L1.1@3267,1550 3267.2,1532.34 3326.86,1474 3440,1474 TP9.1@3450,1484
SW_B2: L2.1 TP10.1 U1.15 U1.16 | length 290.9
  Top Layer w7.87: L2.1@2899.88,1547 L2.1@2911,1558.12
  Top Layer w8: TP10.1@2695,1373 2870,1548 L2.1@2897.73,1548
SW_B3: L3.1 TP11.1 U1.43 U1.44 | length 315
  Top Layer w7.87: L3.1@3221,1957.88 L3.1@3227,1963.88 ; L3.1@3223,1967.88 3256.57,1967.88 3289.98,2001.29 3499.71,2001.29 TP11.1@3511,1990
SW_B4: L4.1 TP12.1 U1.55 U1.56 | length 389.7
  Top Layer w6: TP12.1@2648,2190 2624.85,2166.85 2654.06,2166.85 2850.91,1970 ; 2851,1969.91 2850.91,1970 ; L4.1@2900.1,1970 2874.26,1970 2850.91,1970
SW_B5: L5.1 TP13.1 U1.34 | length 429.1
  Top Layer w7.87: L5.1@3273.88,1679 3294,1658.88 3294,1643 3389,1548 3533.6,1548 3574.6,1507 3595,1507 3600,1512 TP13.1@3585.31,1512 ; 3290,1645 3294,1641
SYNCCLKIN: R32.2 TP8.1 U1.42 | length 1027
  Top Layer w6: U1.42@3219.54,1886.95 U1.42@3220.54,1886.95 3237.54,1886.95 v1(3245,1894.41)
  Signal Layer 1 w6: v1(3888.31,1960) 3888.31,2082.31 TP8.1@3931,2125
  Signal Layer 2 w6: v1(3245,1894.41) 3685.04,1894.41 3744.63,1954 3882.31,1954 v1(3888.31,1960)
  Bottom Layer w6: TP8.1@3931,2125 R32.2@4076.31,2125
TCK: J31.4 U3.100 U4.3 | length 1014
  Signal Layer 1 w5: v1(167,772) 180,785 347,785 v1(360.43,771.57)
  Bottom Layer w5: v1(167,772) 177.79,782.79 177.79,1071.79 206.21,1100.21 482.91,1100.21 U3.100@484.85,1102.15
  Bottom Layer w9: U4.3@332.68,771.57 v1(360.43,771.57) 378.43,771.57 412,738 J31.4@412,645.53
TDI: J31.8 U3.98 U4.6 | length 971.5
  Signal Layer 2 w5: v1(210,585) 223,598 v1(301,598)
  Bottom Layer w5: v1(210,585) 210,588 209,589 209,1050 229.65,1070.65 U3.98@484.85,1070.65 ; v1(301,598) 301,637.24 J31.8@310,646.24 ; J31.8@312,645.53 313,646.53 U4.6@313,718.43
TDO: J31.6 U3.97 U4.5 | length 1009.2
  Bottom Layer w5: U4.5@332.68,718.43 356.92,718.43 362,713.34 362,604 330,572 250,572 226,596 226,1038 244.5,1056.5 383.25,1056.5 383.35,1056.4 385.25,1056.4 385.35,1056.5 449.25,1056.5 450.84,1054.91 U3.97@484.85,1054.91
TMS: J31.2 U3.99 U4.1 | length 1426.2
  Bottom Layer w5: U4.1@293.31,771.57 293.31,777.52 306.7,790.9 384.83,790.9 448.36,727.37 448.36,657.87 J31.2@460,646.24 ; J31.2@462,646.24 462,580.82 431.4,550.23 218.18,550.23 192.12,576.29 192.12,1062.1 216.42,1086.4 U3.99@484.85,1086.4
TRIG_WDG: J7.3 J7.10 U3.63 | length 1191.8
  Signal Layer 1 w5: J7.3@1002,671 1010,679 1010,901.5 1053,944.5 v1(1053,1020)
  Signal Layer 2 w5: J7.3@1002,671 1012,671 1055,714 1659,714 J7.10@1702,671
  Bottom Layer w5: v1(1053,1020) 1053,1066 1057.65,1070.65 U3.63@1091.15,1070.65
USB_ID: R45.2 U5.3 | length 177.8
  Bottom Layer w6: 475,897.56 508.56,864 565.67,864 574.91,873.24 U5.3@574.91,889.69
  Bottom Layer w9: 475,897.56 R45.2@475,941.31
USBD_N: J22.A7 J22.B7 U3.93 U5.2 | length 455.5
  Top Layer w5: J22.B7@338.52,999.46 365.21,999.46 369.17,995.5 370.17,995.5 370.83,995.5 372.83,993.5 373.83,992.5 384.17,982.17 384.17,980.6 388.56,976.21 390.13,976.21 396.41,969.93 J22.A7@405.45,969.93
  Top Layer w6: J22.A7@405.45,969.93 442.93,969.93 473,1000 v1(473,1019)
  Signal Layer 2 w6: v1(473,1019) 569,1019 590,1040 v1(590,1045)
  Bottom Layer w5: U5.2@574.91,909.37 579.69,909.37 591.15,920.83 591.15,921.81 591.29,921.95 591.29,936.16 591.15,936.3 U3.93@591.15,995.85 590,997 v1(590,1045)
USBD_P: J22.A6 J22.B6 U3.94 U5.1 | length 452.7
  Top Layer w5: J22.B6@338.52,979.77 338.75,980 339,979.75 339.25,980 340.25,981 342.25,979 v1(364,979) ; J22.A6@405.45,989.61 427.61,989.61 442,1004 v1(442,1039)
  Bottom Layer w5: v1(364,979) 382,979 v1(442,1039) 511.8,1039 511.9,1038.9 519.54,1046.54 559.46,1046.54 575.4,1030.6 U3.94@575.4,995.85 575.4,930.53 U5.1@573.93,929.06
V3V3: C111.2 J15.7 U13.6 | length 1205.2
  Bottom Layer w11: J15.7@96,1673 43,1726 43,2445 195.56,2597.56 C111.2@336,2597.56 341.87,2591.69 U13.6@388.66,2591.69
V5V0: C112.1 C113.1 J15.9 U14.4 U14.5 U14.16 | length 1362.4
  Signal Layer 2 w18: v1(320,2388.8) 331.2,2400 472,2400 v1(484,2388)
  Bottom Layer w11: J15.9@96,1473 146,1523 146,2335 200,2389 C113.1@219,2389 ; C112.1@219,2438.76 C113.1@219,2401 C113.1@219,2389 ; U14.16@286.02,2388.8 285.81,2389 C113.1@219,2389 ; U14.5@518.3,2388.8 U14.4@518.3,2414.39
  Bottom Layer w18: U14.16@286.02,2388.8 v1(320,2388.8) ; v1@484.01,2389 U14.5@518.3,2388.8
VCC1P8: C109.1 U6.5 U7.3 | length 1018.1
  Signal Layer 1 w11: v1(1123,1903) 1176,1956 1176,2039.87 v1(1123.94,2091.94)
  Signal Layer 2 w11: v1(597,1902) 598,1903 907.5,1903 934.5,1876 970,1876 997,1903 v1(1123,1903)
  Bottom Layer w11: U6.5@436.62,1850 507.44,1850 507.97,1850.56 556.44,1902 v1(597,1902) ; v1@1124,2092 v1(1123.94,2091.94) 1147.56,2068.32 U7.3@1147.56,2047.75
VCCA: C7.1 C36.2 C47.1 C58.1 C69.1 C78.1 C94.1 C99.1 C117.1 J16.1 J17.1 J18.1 J26.1 J28.1 J28.2 J28.3 J28.4 J28.5 J28.6 J28.7 J28.8 Q1.1 Q1.2 Q1.3 R25.2 R33.1 R40.2 R58.1 R93.1 U1.17 U1.26 U1.35 U1.45 U1.54 | length 4919.3
  Top Layer w11: v1(2952,1632) 2954,1632 2956,1630 2958,1632 2959,1631 2960,1632 2962,1630 2970,1638 v1(2977.69,1630.31) 2977.69,1605.91 2978,1605.6 v1(2978,1580) ; 2965.04,1890.23 2966.4,1891.6 ; 2965.04,1934.85 2973.96,1925.94 2973.96,1899.15 2966.4,1891.6 ; v1@2967,1937.6 2967.6,1937 2972,1941.4 v1(2972,1944) ; v1@2977,1896.29 2978,1897.29 ; v1@2979,1894 v1@2979,1896.29 ; 2980,1899.29 2979,1898.29 ; v1(2993,1944) 2993,1936.06 2982.88,1925.94 2982.88,1920.19 2979,1916.31 2980,1915.31 2977.69,1913 2979.65,1911.04 2977,1908.39 2979,1906.39 2979,1898.29 ; v1(3140,1941) 3140,1940.02 3155,1925.02 3152.51,1922.53 3155,1920.05 v1@3155,1892.41 ; v1@3153,1894.41 v1@3155,1892.41 ; v1(3155,1890) v1@3155,1892.41 ; v1(3167,1940) 3167,1932.89 3160.04,1925.94 3160.04,1899.15 3167,1892.19 3167,1889.59 3162.41,1885 v1@3155,1892.41 ; v1@3194,1748.48 3195.13,1749.61 U1.35@3219.81,1749.61 ; 2966.4,1891.6 2970,1888 v1@2978.65,1896.65 ; 2978,1897.29 v1@2978.65,1896.65 ; 2978,1897.29 2979,1898.29 ; v1@2978.65,1896.65 v1@2979,1896.29 ; v1@2978.65,1896.65 v1@2979,1897 ; v1@2979,1896.29 v1@2979,1897 ; v1@2979,1897 2979,1898.29 ; v1@2979,1897 2979.65,1897.65 2979,1898.29
  Top Layer w22: Q1.3@934,2794.95 Q1.2@984,2794.95 Q1.1@1034,2794.95
  Signal Layer 1 w6: v1(3848,2065) 3848,2279.78 3928,2359.78 3928,2479.63 J26.1@3928.37,2480
  Signal Layer 1 w8: v1(567.32,436.44) 567.32,862.32 728,1023 v1(728,1734.27) 728,1824 704,1848 704,1883 728,1907 v1(728,2032)
  Signal Layer 2 w6: v1(3140,1941) 3163,1941 3166,1938 3272,2044 3680,2044 3701,2065 v1(3848,2065)
  Signal Layer 2 w11: v1(728,2032) 729,2033 v1(941,2033)
  Bottom Layer w8: R93.1@670.02,1768 703.82,1734.2 703.9,1734.27 v1(728,1734.27)
  Bottom Layer w11: v1(941,2033) 984,2033 1055,1962 1064.33,1962 1064.33,1957.92 1075.75,1946.5 1091.9,1946.5 1097.9,1952.5 1161.94,1952.5 1187.23,1977.79 1187.23,2001.73 1221,2035.51 1221,2051 1337.63,2167.63 v1(1367,2167.63) v1@1367.63,2167 ; C69.1@2973.53,1908.47 C69.1@2974,1908
  Bottom Layer w15: v1@567,436.76 v1(567.32,436.44) R33.1@567.32,351
  Bottom Layer w22: C7.1@557.59,3100 J28.1@693.2,3100 ; R25.2@1121,2715.18 1184.5,2715.18 C99.1@1186,2713.69
  Bottom Layer w33: C99.1@1186,2713.69 1201.05,2728.74 J28.6@1201.05,3087.22
  other v1: 3155,1584 3146,1630 3165,1630 3195,1741 3244,1748 3195,1760 2980,1888.47
VCCA_S: J12.6 R40.1 | length 1537.9
  Signal Layer 2 w5: v1(3458,1417) 3460,1415 v1(3724,1415)
  Bottom Layer w5: R40.1@3431.5,1425 3433.5,1425 3441.5,1417 v1(3458,1417) ; v1(3724,1415) 3724,1372 3743,1353 4498,1353 4500,1355 4653.5,1201.5 J12.6@4850,1201.5
VIO: Q2.1 R19.1 | length 1278.1
  Signal Layer 1 w8: v1(3801.79,2082) 3801.79,2200.49 3832,2230.7 3832,2349.03 v1(3895.97,2413)
  Signal Layer 2 w8: v1(3895.97,2413) 4315.74,2413 4323,2405.74 v1(4325.71,2405.74)
  Bottom Layer w5: Q2.1@4207.32,2405.47 4265.69,2405.47 ; 4265.96,2405.74 v1(4325.71,2405.74)
  Bottom Layer w8: R19.1@3800.68,2006 3802.65,2006 3808.5,2011.84 3808.5,2013.46 3819.04,2024 3882.25,2024 3884.25,2022 3947.46,2022 3958,2032.54 3958,2047.46 3929.46,2076 3871.43,2076 3864.43,2083 3802.79,2083 v1(3801.79,2082)
VIO_IN: C100.1 C107.2 C108.2 C110.2 J29.8 J30.2 R8.2 R9.2 R14.2 R15.2 R16.2 R17.2 R18.2 R28.2 R29.1 R37.2 R65.1 U10.1 U11.2 U11.5 U11.7 U11.10 U11.14 U12.14 | length 9175.7
  Signal Layer 1 w11: v1(1151.07,1818) 1163,1806.07 v1(1163,1749)
  Signal Layer 1 w22: v1(2139.59,1264.59) 2157.41,1264.59 2210.5,1211.5 2210.5,1170.48 2190.77,1150.75 v1(2190.77,1112.23) ; v1(3680,2100) 3680,1457 3682,1459 3684,1457 v1(3743,1457)
  Signal Layer 1 w33: v1(1289.68,1882.68) v1(1289.68,2233.68) ; v1(1510,1312) v1(1510,1878.04) ; v2(3680,799) v1(3680,1080) 3680,1457
  Signal Layer 2 w22: v2(1115,2232.68) v1(1289.68,2233.68) ; J29.8@3899,799 J29.8@3900,800
  Signal Layer 2 w33: 1280,1879 v1@1502,1879 ; v1(1510,1312) 1560,1312 1649,1223 1914,1223 1962.24,1271.24 2132.94,1271.24 v1(2139.59,1264.59) ; v1(2190.77,1112.23) 2274.77,1112.23 2343,1044 2995,1044 3031,1080 v1(3680,1080) ; v2(3680,799) J29.8@3899,799
  Bottom Layer w6: R8.2@802,607.5 R8.2@801.18,606.69 951.69,606.69 974,629 1381.69,629 ; 1178.62,1285.9 1178.62,1313.49 1182.14,1317 U12.14@1218.51,1317 ; 1550.5,607.69 1551.49,608.67 ; R29.1@2109.68,1111.96 2100,1121.65 2100,1181.83 2105.29,1187.13 U11.14@2120.75,1187.13
  Bottom Layer w8: 1178.62,1285.9 1236.52,1228 1301.54,1228 1369.54,1296 1445,1296 1461,1312 v1(1510,1312) 1560,1312 1630,1242 1630,953.86 1551.49,875.35 1551.49,608.67 ; R29.1@2109.68,1111.96 2111.65,1111.96 2117.5,1117.8 2117.5,1119.77 2122.39,1124.66 2178.34,1124.66 ; v1(2190.77,1112.23) 2203,1124.46 2241.46,1124.46 2262,1145 2262,1179.66 2254.54,1187.13 ; U11.7@2215.24,1187.13 2254.54,1187.13 ; U11.5@2215.24,1218.62 2241.38,1218.62 2254.54,1205.46 2254.54,1187.13 ; C110.2@3746.91,1371.31 v1@3746.91,1457.22
  Bottom Layer w11: R28.2@1113.69,1817.18 1113.69,1818.5 1138.35,1818.5 1138.51,1818.34 1150.73,1818.34 v1(1151.07,1818) ; 1381.69,629 R14.2@1402,608.69 1403,607.69 1550.5,607.69 R18.2@1801,607.69 ; U11.2@2160.12,1226.5 2160.13,1264.06 2160.66,1264.59 ; U11.10@2175.87,1163.5 2175.87,1127.13 v1(2190.77,1112.23) ; C108.2@2184.18,954.9 2188.67,954.9 C108.2@2190.77,957
  Bottom Layer w18: v1(2139.59,1264.59) 2160.66,1264.59
  Bottom Layer w20: C108.2@2190.49,959.24 2191.04,959.79 2191.04,1006.86 2191.04,1111.96 v1(2190.77,1112.23)
  Bottom Layer w22: C100.1@799.68,2312.2 851.52,2312.2 931.04,2232.68 v2(1115,2232.68) J30.2@1115,2166 ; R37.2@1112.1,1749 1151.18,1749 ; v1(1163,1749) 1151.18,1749 ; 1280.5,1878.68 1151,1749.18 1151.18,1749 ; v1(3680,2100) 3680,2103.54 R65.1@3698.46,2122
VOUT_B1: C18.1 C24.2 C29.2 C35.2 C39.2 C46.1 C50.1 C55.1 C55.3 C63.1 C63.3 C68.1 C68.3 C74.1 C74.3 C79.1 C103.1 J1.1 J12.1 J23.1 J24.2 J32.1 J42.2 J43.1 L1.2 R1.2 | length 2623.1
  Signal Layer 1 w6: 3311,379 3312,380 v1(3312,1018) ; J1.1@3371,195 3371,301
  Signal Layer 1 w8: 3311,379 3311,361 3371,301 3832,301 3911,380 J32.1@3911,560.88
  Signal Layer 2 w8: J32.1@3911,560.88 4710.38,560.88 J12.1@4851,701.5
  Bottom Layer w7.87: R1.2@3289,1018 v1(3312,1018)
  other v2: 3223,1156 3258,1157 3100,1159 3143,1159 3098,1200 3141,1200 3223,1201 3258,1202 3098,1245 3141,1245 3222,1246 3259,1246 3254,1285 3192,1293 3097,1298 3140,1298 3096,1345 3139,1345 3255,1345 3192,1346 3096,1387 3139,1387 3218,1393 3254.28,1395
VOUT_B2: C19.1 C25.2 C30.2 C40.2 C43.1 C51.1 C56.1 C60.1 C60.3 C65.1 C65.3 C71.1 C71.3 C76.1 C76.3 C102.1 J2.1 J12.2 J23.2 J33.1 J39.3 J42.1 L2.2 R3.2 | length 4350.4
  Signal Layer 1 w5: J33.1@2318,556 2318,388 2515,191 2634.57,191 J2.1@2639.57,196 2645,196 2943,494 2943,979 2974,1010 v1(3050,1010)
  Signal Layer 2 w5: J33.1@2318,556 2649,556 2818,725 4773.5,725 J12.2@4850,801.5
  Bottom Layer w5: 2911,979 2931,979 2944,992 ; J23.2@2961.09,1346 J23.2@2961.09,1385.22 ; R3.2@3016.68,1012 3018.69,1010 v1(3050,1010)
  other v1: 2864,558
  other v3: 2885.04,1131 2920.04,1131 2994,1131 3039,1131 2885.04,1185 2918,1185 2994,1185 3039,1185 2886,1239 2918,1239 2995,1265 3030,1265 2950,1292 2888,1293 2995,1319 3030,1319 2950,1347 2888,1348 2995,1359 3030,1359 2926,1394 2995,1394 3030,1394 2887,1402
VOUT_B3: C20.1 C26.2 C31.2 C41.2 C44.1 C52.1 C57.1 C61.1 C61.3 C66.1 C66.3 C72.1 C72.3 C77.1 C77.3 C104.1 J3.1 J12.3 J24.1 J25.2 J34.1 J40.3 J43.2 J44.1 L3.2 R5.2 | length 4055.2
  Signal Layer 1 w7.87: v1(3246,2493) 3248,2493 3547,2792 3547,3250.57 J3.1@3550.43,3254 ; J34.1@3905,2955 4054,2955 4452,2557 4452,1299.5 J12.3@4850,901.5
  Signal Layer 2 w7.87: J3.1@3550.43,3254 3551.43,3255 3790,3255 3905,3140 J34.1@3905,2955
  Bottom Layer w22: R5.2@3243.68,2471 3245,2472.31 3246,2473.31 v1(3246,2493) ; v1(3450,3115) 3450.31,3114.69 C41.2@3450.31,3091
  other v2: 3247.96,2141.05 3097,2160 3135,2160 3212,2160 3248,2187 3097,2197 3135,2197 3212,2197 3097,2232.68 3135,2232.68 3212,2232.68 3247.96,2232.7 3248.07,2275.35 3098,2283 3135.82,2283 3212,2283 3139,2320 3101,2321 3213,2321 3248.1,2321.3 3138.92,2364 3101,2365 3212.61,2366.7 3248.07,2367
VOUT_B4: C21.1 C27.2 C32.2 C37.2 C42.2 C48.1 C53.1 C59.1 C59.3 C64.1 C64.3 C70.1 C70.3 C75.1 C75.3 C105.1 J4.1 J12.4 J25.1 J35.1 J41.3 J44.2 L4.2 R7.2 | length 5582.6
  Signal Layer 1 w6: J4.1@2827.43,3254 2880,3201.43 2880,2936.98 2934,2882.98 v1(2934,2498)
  Signal Layer 1 w7.87: J4.1@2827.43,3254 2976.43,3403 3966,3403 4800,2569 4800,1051.5 J12.4@4850,1001.5
  Signal Layer 2 w7.87: J35.1@2330.01,2824.07 2326,2828.08 2326,3010.55 2484.61,3169.16 2704.32,3169.16 2776.36,3241.2 2814.63,3241.2 J4.1@2827.43,3254
  Bottom Layer w6: v1(2934,2498) 2934,2474.31 R7.2@2934.31,2474
  other v2: 2894,2149 2922.92,2163 3017,2164 2894.08,2191 2923,2205 3017,2206 2894.08,2235 2922.92,2249 3016,2250 2895.92,2280 2928,2283 3004,2283 3035,2283 2896,2322 2927,2322 3004,2322 3035,2322 2896,2366 2926.92,2366 3004,2366 3034.92,2366
  other v3: 2729.62,3341 2982,3341
VOUT_B5: C22.1 C28.2 C33.2 C34.2 C38.1 C45.1 C49.1 C54.1 C54.3 C62.1 C62.3 C67.1 C67.3 C73.1 C73.3 C101.1 J5.1 J12.5 J36.1 L5.2 R67.2 | length 2263.4
  Signal Layer 1 w7.87: J5.1@4753,1666.15 J5.1@4753,1669.18
  Signal Layer 2 w6: 4756,1195.5 J12.5@4850,1101.5
  Signal Layer 2 w7.87: v1@3940,2041 v1(3940,2040) 3970,2010 4622,2010 ; J36.1@4622.18,2311 4622.18,1863.41 4756,1729.59 4756,1195.5
  Bottom Layer w7.87: R67.2@3773.89,2043.76 3775.46,2045.33 3780.8,2040 v1(3940,2040)
  Bottom Layer w22: C73.3@4760.31,1764.84 4759.08,1763.61 4759.08,1744.6 4769.6,1734.08 4790.39,1734.08 4800.92,1744.6 4800.92,1763.61 C73.1@4799.68,1764.84
  other v2: 3749,1638 3805,1638 3860,1638 3805,1684 3860,1684 3749,1685 4299,1732 3749,1735 3805,1735 3860,1735 3750,1817.18 3797,1817.18 3840,1818 3887,1818 3751,1873.18 3797,1873.18 3841,1874 3887,1874 3751,1928.18 3797,1928.18 3841,1929 3887,1929
VOUT_LDO1: C8.1 J13.1 J14.1 U1.13 | length 3027.2
  Top Layer w9: C8.1@2854.69,1630 2855.56,1630.81 2856.24,1631.43 2872,1646 2898.79,1646 2903.52,1650.73 U1.13@2912.46,1650.73 ; C8.1@2857.56,1630 C8.1@2863,1630
  Top Layer w11: J14.1@2446,1513 2446,1515 J14.1@2447,1516 ; 2684,1575 2701.5,1592.5 2825.5,1592.5 C8.1@2863,1630
  Top Layer w22: J14.1@2436,1516 J14.1@2447,1516
  Top Layer w55: J14.1@2447,1516 2654,1518 2713,1577
  Signal Layer 1 w6: v1(1852.75,1516.25) 1852.75,3342.75 J13.1@1860,3350
  Signal Layer 2 w6: v1(1852.75,1516.25) 1871,1498 2072.41,1498 2088.41,1482 2180.96,1482 2181.96,1481 2196.04,1481 2197.04,1482 2210.25,1482 2244.25,1516 J14.1@2436,1516
VOUT_LDO2: C10.1 J13.2 J14.2 U1.11 | length 2911.3
  Top Layer w11: 2765.19,1654.77 2835.86,1654.77 C10.1@2869.36,1688.27 ; C10.1@2862.56,1689 2863.29,1688.27 C10.1@2869.36,1688.27 ; C10.1@2871.65,1690.56 C10.1@2869.36,1688.27 ; 2901.98,1688.27 C10.1@2869.36,1688.27 ; U1.11@2903.8,1689.5 U1.11@2913.46,1689.5
  Top Layer w28: J14.2@2435,1616 2473.77,1654.77 2765.19,1654.77
  Signal Layer 1 w6: v1@1877.45,1641 1880.85,3142.86 1960,3222.02 J13.2@1960,3351
  Signal Layer 2 w6: v1(1877,1641) 1877,1622 1914,1585 1975,1585 2062,1672 2106,1672 2162,1616 J14.2@2435,1616
VOUT_LDO3: C11.1 J13.3 J14.3 J20.3 U1.9 | length 3309.5
  Top Layer w9: 2723,1765 2735,1753 2840.49,1753
  Top Layer w11: 2840.49,1753 2863.56,1729.93 2882.08,1729.93 ; 2885.51,1729.5 2901.49,1729.5 2901.92,1729.93 2939.01,1729.93 v1@2938.94,1730 ; v1@2937,1731.94 v1@2938.94,1730 ; v1(2940,1730) v1@2938.94,1730
  Top Layer w40: 2473.25,1749.94 2725,1752
  Top Layer w44: J14.3@2435,1716 2439.55,1716 2470.67,1747.12 2473.25,1749.94
  Signal Layer 1 w5: J13.3@2060,3351 2060,3254 2010,3204 2010,1693.61 2073.61,1630 J20.3@2084,1630 ; J20.3@2084,1651.26 J20.3@2106.3,1651.26
  Signal Layer 2 w5: J20.3@2084,1630 2133.15,1630 2224.77,1538.38 2383.96,1538.38 2401.55,1555.98 2458.04,1555.98 2506.56,1604.5 2539.34,1604.5 2609.84,1675 2780.16,1675 2791.43,1686.27 2896.43,1686.27 2940,1729.84 v1(2940,1730)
